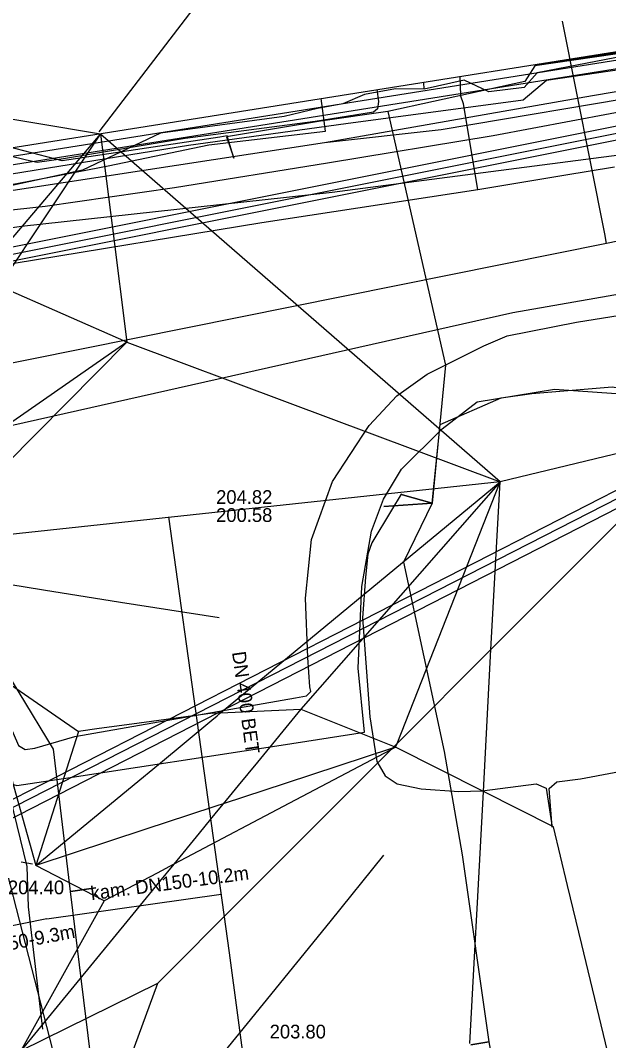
# Model space of a CAD drawing. Extents: x -600309 to -598967, y -1161267 to -1160292.
# Drawn here: x -599317.2 to -599283, y -1161181.8 to -1161122.4 of the extents above; entities that cross this region are included whole.
import ezdxf

# ---------------------------------------------------------------- set-up
doc = ezdxf.new("R2010")
doc.units = 0
for name, color, linetype in [('Vrstva 10', 7, 'Continuous'), ('Vrstva 12', 7, 'Continuous'), ('Vrstva 13', 7, 'Continuous'), ('Vrstva 16', 7, 'Continuous'), ('Vrstva 19', 7, 'Continuous'), ('Vrstva 29', 7, 'Continuous'), ('Vrstva 30', 7, 'Continuous'), ('Vrstva 42', 7, 'Continuous'), ('Vrstva 44', 7, 'Continuous'), ('Vrstva 54', 7, 'Continuous'), ('Vrstva 55', 7, 'Continuous'), ('Vrstva 58', 7, 'Continuous'), ('Vrstva 9', 7, 'Continuous')]:
    doc.layers.add(name, color=color, linetype=linetype)

msp = doc.modelspace()

# ---------------------------------------------------------------- linework, layer by layer
at = {"layer": 'Vrstva 10'}
for p, q in [((-599276.131, -1161127.316), (-599342.313, -1161140.557)), ((-599275.975, -1161128.1), (-599342.157, -1161141.341))]:
    msp.add_line(p, q, dxfattribs=at)
for points in [[(-599325.68, -1161171.87), (-599263.13, -1161139.86)], [(-599325.11, -1161172.66), (-599263.04, -1161140.87)]]:
    msp.add_lwpolyline(points, dxfattribs=at)
at = {"layer": 'Vrstva 12'}
for points in [[(-599360.51, -1161096.34), (-599358.98, -1161104.14), (-599358.41, -1161105.92), (-599355.06, -1161110.01), (-599349.43, -1161115.82), (-599346.87, -1161119.12), (-599341.43, -1161125.16), (-599332.9, -1161131.91), (-599321.79, -1161132.77), (-599312.13, -1161130.91), (-599306.26, -1161129.68), (-599299.48, -1161128.89), (-599299.72, -1161126.98)], [(-599299.54, -1161129.54), (-599283.93, -1161126.81), (-599274.54, -1161125.22)], [(-599292.75, -1161128.79), (-599280.31, -1161126.7), (-599277.95, -1161126.35)], [(-599299.54, -1161129.54), (-599292.75, -1161128.79)], [(-599323.24, -1161133.18), (-599299.54, -1161129.54)], [(-599275.47, -1161137.17), (-599288.56, -1161139.47), (-599332.64, -1161149.38), (-599346.78, -1161140.39), (-599350.45, -1161142.1)], [(-599261.28, -1161140.14), (-599263.08, -1161140.36), (-599325.43, -1161172.22), (-599326.65, -1161173.48), (-599327.46, -1161176), (-599334.7, -1161189.15), (-599335.01, -1161190.85)], [(-599297.2, -1161163.88), (-599297.58, -1161160.16), (-599297.35, -1161155.39), (-599296.8, -1161152.18), (-599296.1, -1161150.31), (-599295.05, -1161148.56), (-599292.68, -1161146.21), (-599290.64, -1161144.65), (-599286.15, -1161143.9), (-599282.56, -1161144.17), (-599277.13, -1161145.23), (-599273.28, -1161146.7)], [(-599319.77, -1161165.13), (-599319.29, -1161166.03), (-599318.49, -1161166.67), (-599317.43, -1161166.99), (-599314.72, -1161166.57), (-599302.06, -1161164.63), (-599297.2, -1161163.88)]]:
    msp.add_lwpolyline(points, dxfattribs=at)
at = {"layer": 'Vrstva 13'}
for points in [[(-599283.11, -1161135.425), (-599283.222, -1161134.862), (-599285.676, -1161122.491)], [(-599240.916, -1161130.896), (-599268.603, -1161135.413), (-599277.204, -1161134.212), (-599283.11, -1161135.425), (-599319.773, -1161142.795)]]:
    msp.add_lwpolyline(points, dxfattribs=at)
at = {"layer": 'Vrstva 16'}
for points in [[(-599327.49, -1161135.23), (-599325.48, -1161135.59), (-599317.17, -1161134.41), (-599299.08, -1161132.44), (-599292.83, -1161131.63), (-599273.86, -1161129.17), (-599251.23, -1161123.99)], [(-599302.349, -1161232.808), (-599308.99, -1161207.05), (-599324.87, -1161145.39), (-599327.49, -1161135.23)]]:
    msp.add_lwpolyline(points, dxfattribs=at)
at = {"layer": 'Vrstva 19'}
for points in [[(-599291.45, -1161127.29), (-599291.59, -1161126.85), (-599291.62, -1161126.21), (-599291.643, -1161125.711)], [(-599290.6, -1161132.28), (-599291.45, -1161127.29)], [(-599318.27, -1161137.08), (-599317.6, -1161136.57), (-599303.17, -1161134.21), (-599290.6, -1161132.28), (-599285.61, -1161131.45), (-599282.649, -1161130.966)]]:
    msp.add_lwpolyline(points, dxfattribs=at)
at = {"layer": 'Vrstva 29'}
msp.add_lwpolyline([(-599158.303, -1161104.988), (-599325.905, -1161131.661), (-599336.75, -1161127.83), (-599365.633, -1161095.812), (-599414.895, -1161072.929)], dxfattribs=at)
at = {"layer": 'Vrstva 30'}
for points in [[(-599414.684, -1161072.476), (-599365.33, -1161095.401), (-599336.464, -1161127.401), (-599325.858, -1161131.147), (-599158.381, -1161104.495)], [(-599158.224, -1161105.482), (-599325.952, -1161132.175), (-599337.036, -1161128.259), (-599365.936, -1161096.223), (-599415.106, -1161073.382)]]:
    msp.add_lwpolyline(points, dxfattribs=at)
at = {"layer": 'Vrstva 42'}
for points in [[(-599296.478, -1161126.465), (-599296.38, -1161127.16), (-599296.44, -1161127.59), (-599296.67, -1161127.79), (-599300.07, -1161128.33), (-599307.64, -1161129.31), (-599314.73, -1161130.49), (-599316.26, -1161130.72), (-599316.88, -1161130.58), (-599317.91, -1161130.32), (-599324.39, -1161131.25), (-599326.12, -1161131.48), (-599326.57, -1161131.42), (-599334.04, -1161128.67), (-599336.39, -1161127.69), (-599336.62, -1161127.5), (-599341.05, -1161122.63), (-599345.64, -1161117.62)], [(-599317.18, -1161171.429), (-599316.537, -1161171.534)], [(-599317.18, -1161171.429), (-599316.537, -1161171.534)]]:
    msp.add_lwpolyline(points, dxfattribs=at)
at = {"layer": 'Vrstva 44'}
for points in [[(-599357.15, -1161131.46), (-599356.69, -1161132.04), (-599355.92, -1161132.23), (-599340.76, -1161126.52), (-599337.6, -1161127.98), (-599334.3, -1161129.65), (-599325.84, -1161132.1), (-599322.56, -1161132.15), (-599307.44, -1161129.7), (-599298.29, -1161128.45), (-599287.97, -1161127.06), (-599286.6, -1161125.91), (-599274.96, -1161124.22), (-599259.04, -1161121.46), (-599242.21, -1161118.98), (-599232.167, -1161117.766), (-599230.06, -1161117.26), (-599228.86, -1161117.2)], [(-599321.99, -1161156.109), (-599320.39, -1161157.65), (-599319.52, -1161158.76), (-599319.4, -1161159.03), (-599317.97, -1161163.22), (-599317.34, -1161164.65), (-599316.95, -1161164.88), (-599316.39, -1161164.81), (-599314.06, -1161164.13), (-599301.21, -1161161.88), (-599300.58, -1161161.77), (-599300.32, -1161161.5), (-599300.38, -1161161.24), (-599300.5, -1161159.53), (-599300.63, -1161156.08), (-599300.29, -1161152.66), (-599299.07, -1161149.28), (-599296.94, -1161146.02), (-599295.32, -1161144.3), (-599293.55, -1161143.03), (-599290.26, -1161141.38), (-599288.9, -1161140.81), (-599284.87, -1161140), (-599281.83, -1161139.52)]]:
    msp.add_lwpolyline(points, dxfattribs=at)
at = {"layer": 'Vrstva 54'}
for points in [[(-599289.387, -1161098.523), (-599312.676, -1161128.921)], [(-599312.57, -1161129.07), (-599342.81, -1161124)], [(-599317.75, -1161135.17), (-599312.57, -1161129.07)], [(-599316.54, -1161135.04), (-599312.57, -1161129.07)], [(-599307.15, -1161133.78), (-599312.57, -1161129.07)], [(-599312.57, -1161129.07), (-599311.88, -1161134.54)], [(-599298.52, -1161141.29), (-599307.15, -1161133.78)], [(-599318.46, -1161137.92), (-599316.54, -1161135.04)], [(-599311.88, -1161134.54), (-599311.032, -1161141.178)], [(-599311.032, -1161141.178), (-599318.46, -1161137.92)], [(-599311.032, -1161141.178), (-599319.48, -1161147.03)], [(-599318.06, -1161148.27), (-599311.032, -1161141.178)], [(-599311.032, -1161141.178), (-599301.71, -1161144.66)], [(-599289.31, -1161149.3), (-599298.52, -1161141.29)], [(-599301.71, -1161144.66), (-599289.31, -1161149.3)], [(-599277.16, -1161146.38), (-599289.84, -1161159.06)], [(-599277.16, -1161146.38), (-599289.31, -1161149.3)], [(-599305.58, -1161162.75), (-599289.31, -1161149.3)], [(-599289.31, -1161149.3), (-599304.29, -1161150.91)], [(-599289.31, -1161149.3), (-599300.91, -1161162.54)], [(-599295.3, -1161164.53), (-599289.31, -1161149.3)], [(-599289.84, -1161159.06), (-599289.31, -1161149.3)], [(-599304.29, -1161150.91), (-599314.93, -1161152.05)], [(-599314.93, -1161152.05), (-599318, -1161152.38)], [(-599317.91, -1161155.27), (-599315.89, -1161155.59)], [(-599315.89, -1161155.59), (-599311.4, -1161156.3)], [(-599311.4, -1161156.3), (-599305.66, -1161157.21)], [(-599289.84, -1161159.06), (-599295.3, -1161164.53)], [(-599290.28, -1161167.33), (-599289.84, -1161159.06)], [(-599319.66, -1161159.85), (-599316.33, -1161171.63)], [(-599319.66, -1161159.85), (-599313.85, -1161163.83)], [(-599306.04, -1161162.77), (-599310.74, -1161163.41)], [(-599306.09, -1161163.18), (-599305.78, -1161162.92)], [(-599306.04, -1161162.77), (-599305.58, -1161162.75)], [(-599305.78, -1161162.92), (-599305.58, -1161162.75)], [(-599305.58, -1161162.75), (-599300.91, -1161162.54)], [(-599300.91, -1161162.54), (-599303.44, -1161165.63)], [(-599300.91, -1161162.54), (-599295.48, -1161164.71)], [(-599310.74, -1161163.41), (-599312.65, -1161163.67)], [(-599309.2, -1161165.75), (-599306.09, -1161163.18)], [(-599313.85, -1161163.83), (-599316.33, -1161171.63)], [(-599312.65, -1161163.67), (-599313.85, -1161163.83)], [(-599295.39, -1161164.75), (-599295.67, -1161164.9)], [(-599295.48, -1161164.71), (-599295.58, -1161164.81)], [(-599295.39, -1161164.75), (-599295.58, -1161164.81)], [(-599295.3, -1161164.53), (-599295.48, -1161164.71)], [(-599295.48, -1161164.71), (-599295.39, -1161164.75)], [(-599295.39, -1161164.75), (-599295.3, -1161164.53)], [(-599290.28, -1161167.33), (-599295.39, -1161164.75)], [(-599295.58, -1161164.81), (-599301.83, -1161166.87)], [(-599295.67, -1161164.9), (-599300.87, -1161167.64)], [(-599295.67, -1161164.9), (-599299.51, -1161168.74)], [(-599295.58, -1161164.81), (-599295.67, -1161164.9)], [(-599310.61, -1161166.92), (-599309.2, -1161165.75)], [(-599303.44, -1161165.63), (-599304.56, -1161166.99)], [(-599316.33, -1161171.63), (-599310.61, -1161166.92)], [(-599301.83, -1161166.87), (-599305.43, -1161168.05)], [(-599304.56, -1161166.99), (-599305.43, -1161168.05)], [(-599300.87, -1161167.64), (-599308.31, -1161171.57)], [(-599290.61, -1161173.44), (-599290.28, -1161167.33)], [(-599286.21, -1161169.38), (-599290.28, -1161167.33)], [(-599305.85, -1161168.19), (-599307.44, -1161168.71)], [(-599305.43, -1161168.05), (-599305.85, -1161168.19)], [(-599305.43, -1161168.05), (-599305.83, -1161168.54)], [(-599307.44, -1161168.71), (-599309.93, -1161169.53)], [(-599305.83, -1161168.54), (-599306.82, -1161169.75)], [(-599299.51, -1161168.74), (-599303.36, -1161172.59)], [(-599285.38, -1161172.81), (-599286.21, -1161169.38)], [(-599309.93, -1161169.53), (-599316.33, -1161171.63)], [(-599306.82, -1161169.75), (-599308.31, -1161171.57)], [(-599299.21, -1161174.91), (-599296.08, -1161171.04)], [(-599312.35, -1161173.7), (-599316.33, -1161171.63)], [(-599308.31, -1161171.57), (-599309.27, -1161172.08)], [(-599308.31, -1161171.57), (-599309.14, -1161172.58)], [(-599309.27, -1161172.08), (-599312.35, -1161173.7)], [(-599309.14, -1161172.58), (-599310.86, -1161174.68)], [(-599303.36, -1161172.59), (-599305.72, -1161174.96)], [(-599284.56, -1161176.23), (-599285.38, -1161172.81)], [(-599290.82, -1161177.32), (-599290.61, -1161173.44)], [(-599312.35, -1161173.7), (-599317.21, -1161182.42)], [(-599310.86, -1161174.68), (-599317.21, -1161182.42)], [(-599305.72, -1161174.96), (-599307.94, -1161177.18)], [(-599303.09, -1161179.69), (-599299.21, -1161174.91)], [(-599280.91, -1161191.39), (-599284.56, -1161176.23)], [(-599307.94, -1161177.18), (-599309.26, -1161178.5)], [(-599291.07, -1161182.01), (-599290.82, -1161177.32)], [(-599309.26, -1161178.5), (-599317.21, -1161182.42)], [(-599309.26, -1161178.5), (-599310.83, -1161182.79)], [(-599305.63, -1161182.82), (-599303.09, -1161179.69)]]:
    msp.add_lwpolyline(points, dxfattribs=at)
at = {"layer": 'Vrstva 55'}
for p, q in [((-599316.84, -1161171.69), (-599318.76, -1161163.85)), ((-599316.76, -1161174.05), (-599316.84, -1161171.69)), ((-599315.92, -1161181.16), (-599316.76, -1161174.05))]:
    msp.add_line(p, q, dxfattribs=at)
for points in [[(-599305.628, -1161129.235), (-599314.8, -1161130.62), (-599317.93, -1161129.8), (-599326.53, -1161131.21), (-599336.75, -1161127.81), (-599345.39, -1161117.66), (-599344.35, -1161116.93)], [(-599281.59, -1161123.58), (-599282.38, -1161124.31), (-599287.29, -1161125.09), (-599287.87, -1161125.99), (-599295.85, -1161127.74), (-599299.76, -1161128.31), (-599305.24, -1161129.21), (-599304.809, -1161130.458), (-599305.2, -1161129.17), (-599305.628, -1161129.235)], [(-599281.59, -1161123.58), (-599281.54, -1161124.26), (-599287.29, -1161125.09), (-599287.87, -1161125.99), (-599295.85, -1161127.74), (-599292.48, -1161142.52), (-599293.26, -1161150.54), (-599294.998, -1161150.062)], [(-599294.998, -1161150.062), (-599293.26, -1161150.54), (-599292.803, -1161145.962), (-599289.24, -1161144.42), (-599287.47, -1161144.16), (-599282.78, -1161143.78), (-599278.57, -1161144.48), (-599278.729, -1161145.643), (-599278.57, -1161144.5), (-599274.917, -1161145.14), (-599268.471, -1161147.265), (-599258.735, -1161151.996)], [(-599294.998, -1161150.062), (-599293.26, -1161150.54), (-599296.087, -1161150.744), (-599293.26, -1161150.54), (-599294.94, -1161153.98), (-599292.56, -1161165), (-599291.513, -1161171.012), (-599289.958, -1161181.902), (-599291.016, -1161182.088), (-599289.958, -1161181.902), (-599288.651, -1161189.12), (-599296.06, -1161194), (-599311.1, -1161199.4), (-599314.318, -1161173.16), (-599312.841, -1161172.939), (-599314.318, -1161173.16), (-599315.31, -1161164.86), (-599323.31, -1161151.68), (-599326.34, -1161151.76)], [(-599294.998, -1161150.062), (-599295.064, -1161150.016), (-599295.632, -1161150.951), (-599296.776, -1161152.861), (-599297.012, -1161153.522), (-599297.137, -1161154.849), (-599297.312, -1161157.229), (-599296.896, -1161162.991), (-599296.491, -1161165.593), (-599296.008, -1161166.415), (-599295.301, -1161166.891), (-599293.904, -1161167.179), (-599291.715, -1161167.324), (-599290.363, -1161167.3), (-599287.214, -1161166.882), (-599286.636, -1161167.129), (-599286.272, -1161169.405), (-599286.451, -1161167.148), (-599286.009, -1161166.777), (-599284.624, -1161166.6), (-599280.391, -1161165.797)]]:
    msp.add_lwpolyline(points, dxfattribs=at)
at = {"layer": 'Vrstva 58'}
for points in [[(-599227.21, -1161115.61), (-599228.15, -1161115.76), (-599238.5, -1161117.44), (-599239.34, -1161117.59), (-599244.56, -1161118.46), (-599249.93, -1161119.49), (-599255.19, -1161120.34), (-599256.12, -1161120.19), (-599270.52, -1161122.47), (-599271.52, -1161122.58), (-599278.85, -1161123.78), (-599279.99, -1161124.08), (-599280.33, -1161124.18), (-599287.15, -1161125.5), (-599287.9, -1161126.34), (-599289.97, -1161126.59), (-599291.41, -1161125.92), (-599293.73, -1161126.45)], [(-599346.76, -1161120.11), (-599336.94, -1161129.78), (-599332.41, -1161132.21), (-599327.32, -1161133.88), (-599322.77, -1161134.02), (-599315.8, -1161133.25), (-599308.27, -1161132.17), (-599299.35, -1161130.74), (-599289.71, -1161129.14), (-599280.64, -1161127.43)], [(-599293.73, -1161126.45), (-599295.39, -1161126.43), (-599297.21, -1161126.75), (-599298.46, -1161127.3), (-599299.94, -1161127.56), (-599301.87, -1161128.03), (-599309.08, -1161129), (-599313.61, -1161131.16), (-599319.89, -1161132.51), (-599321.02, -1161132.35), (-599322.91, -1161131.47), (-599326.379, -1161131.801), (-599330.24, -1161130.39), (-599333.108, -1161130.303), (-599335.83, -1161129.18), (-599337.66, -1161127.35), (-599341.06, -1161123.24), (-599344.18, -1161119.69)], [(-599293.73, -1161126.45), (-599293.75, -1161126.05)]]:
    msp.add_lwpolyline(points, dxfattribs=at)
at = {"layer": 'Vrstva 9'}
for p, q in [((-599342.235, -1161140.949), (-599276.053, -1161127.708)), ((-599315.7, -1161174.74), (-599305.555, -1161173.31)), ((-599315.7, -1161174.74), (-599324.83, -1161176.61))]:
    msp.add_line(p, q, dxfattribs=at)
msp.add_lwpolyline([(-599308.603, -1161151.335), (-599305.082, -1161176.728), (-599304.067, -1161184.28)], dxfattribs=at)

# ---------------------------------------------------------------- texts
at = {"layer": 'Vrstva 12'}
for s, p in [('204.82', (-599305.839, -1161150.589)), ('200.58', (-599305.839, -1161151.639)), ('204.40', (-599317.958, -1161173.315)), ('203.80', (-599302.722, -1161181.708))]:
    msp.add_text(s, height=0.8, dxfattribs=at).set_placement(p)
for s, rotation, p in [('DN 400 BET', 277.89952, (-599304.917, -1161159.227)), ('kam. DN150-10.2m', 7.50099, (-599313.087, -1161173.663)), ('kam. DN150-9.3m', 10.83868, (-599322.524, -1161177.473))]:
    msp.add_text(s, height=0.8, rotation=rotation, dxfattribs=at).set_placement(p)

doc.saveas('drawing.dxf')
